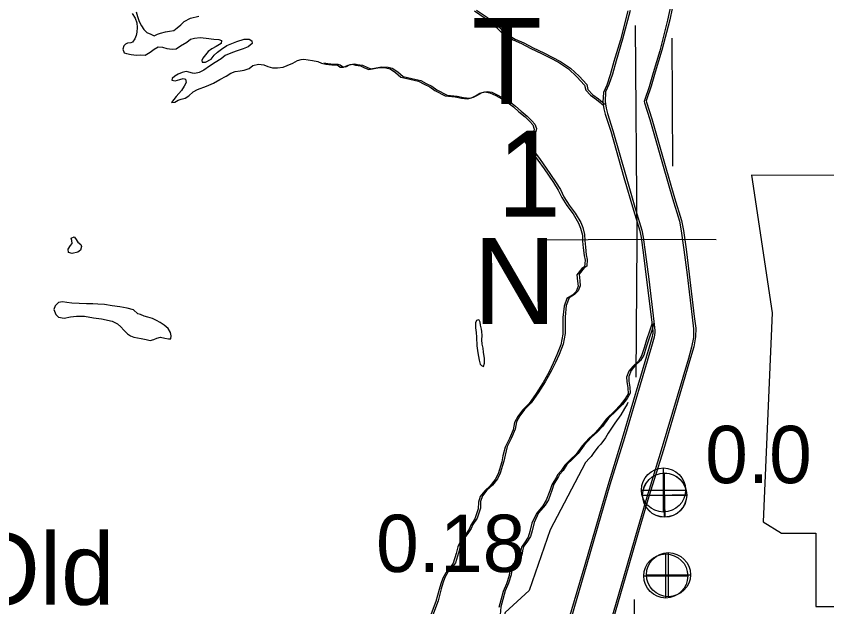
# Model space of a CAD drawing. Extents: x 1127717 to 1741049, y 2026793 to 2244711.
# Drawn here: x 1243987 to 1246972, y 2125542 to 2127719 of the extents above; entities that cross this region are included whole.
import ezdxf

# ---------------------------------------------------------------- set-up
doc = ezdxf.new("R2010")
doc.units = 0
for name, color, linetype in [('10', 7, 'Continuous'), ('2', 7, 'Continuous'), ('21', 7, 'Continuous'), ('25', 7, 'Continuous'), ('26', 7, 'Continuous'), ('30', 7, 'Continuous'), ('5', 7, 'Continuous'), ('58', 7, 'Continuous'), ('9', 7, 'Continuous')]:
    doc.layers.add(name, color=color, linetype=linetype)

msp = doc.modelspace()

# ---------------------------------------------------------------- linework, layer by layer
at = {"layer": '10'}
for points in [[(1246412.5, 2127829.6), (1246385.7, 2127703.7), (1246356.7, 2127591.2), (1246332.3, 2127510.3), (1246317.9, 2127458.3), (1246300.7, 2127408.5), (1246299, 2127404.7), (1246300.3, 2127399.3), (1246320.2, 2127338.8), (1246369, 2127166.2), (1246403.7, 2127047.3), (1246429, 2126963.9), (1246436, 2126927.3), (1246445.7, 2126858.2), (1246457.4, 2126765.6), (1246475.9, 2126610.1), (1246481.7, 2126566.4), (1246481, 2126535.3), (1246474, 2126498.6), (1246462.1, 2126457.2), (1246362.3, 2126119.1), (1246308.9, 2125945.9), (1246276, 2125832.9), (1246224.7, 2125655.6), (1246156.5, 2125423.3)], [(1246420.3, 2127831.9), (1246393.6, 2127706), (1246364.5, 2127593.5), (1246340.2, 2127512.6), (1246325.7, 2127460.6), (1246308.6, 2127410.8), (1246306.8, 2127407), (1246308.2, 2127401.6), (1246328.1, 2127341.1), (1246376.8, 2127168.5), (1246411.5, 2127049.6), (1246436.8, 2126966.2), (1246443.8, 2126929.6), (1246453.5, 2126860.5), (1246465.3, 2126767.9), (1246483.7, 2126612.4), (1246489.5, 2126568.7), (1246488.8, 2126537.6), (1246481.8, 2126500.9), (1246469.9, 2126459.5), (1246370.1, 2126121.4), (1246316.8, 2125948.2), (1246283.8, 2125835.2), (1246232.5, 2125657.9), (1246164.4, 2125425.6)], [(1246239.7, 2127738.1), (1246212.2, 2127631.6), (1246188.2, 2127551.9), (1246174.6, 2127502.9), (1246161.4, 2127464.7), (1246149.2, 2127438.3), (1246147.8, 2127402.2), (1246151.1, 2127377.6), (1246156.2, 2127357.5), (1246176.7, 2127295), (1246224.8, 2127124.9), (1246259.9, 2127004.5), (1246283.1, 2126928), (1246287.9, 2126902.8), (1246297, 2126838.3), (1246308.6, 2126747.3), (1246327.1, 2126591.4), (1246331.5, 2126558.2), (1246331.3, 2126551.3), (1246327.9, 2126533.5), (1246318, 2126499.2), (1246218.7, 2126162.4), (1246165.3, 2125989), (1246131.9, 2125874.8), (1246080.6, 2125697.5), (1246012.5, 2125465.1)], [(1246247.5, 2127740.4), (1246220, 2127633.9), (1246196.1, 2127554.2), (1246182.5, 2127505.2), (1246169.2, 2127467), (1246157, 2127440.6), (1246155.6, 2127404.5), (1246159, 2127379.9), (1246164, 2127359.8), (1246184.6, 2127297.3), (1246232.6, 2127127.2), (1246267.7, 2127006.8), (1246291, 2126930.3), (1246295.8, 2126905.1), (1246304.9, 2126840.6), (1246316.4, 2126749.6), (1246334.9, 2126593.7), (1246339.3, 2126560.5), (1246339.2, 2126553.5), (1246335.8, 2126535.8), (1246325.9, 2126501.5), (1246226.5, 2126164.7), (1246173.1, 2125991.3), (1246139.8, 2125877), (1246088.5, 2125699.8), (1246020.3, 2125467.4)]]:
    msp.add_lwpolyline(points, dxfattribs=at)
at = {"layer": '2'}
msp.add_line((1246405.6, 2127166.5), (1246402.2, 2127638.5), dxfattribs=at)
msp.add_lwpolyline([(1246239.7, 2126294.9), (1246236.2, 2126289.7), (1246227.1, 2126273.5), (1246213.6, 2126250.2), (1246191.9, 2126219.3), (1246167.2, 2126182.2), (1246157.1, 2126165.5), (1246139.9, 2126142), (1246130, 2126132.4), (1246114.2, 2126110.4), (1246104.5, 2126096.5), (1246098.1, 2126089.5), (1246083.2, 2126074.6), (1245952.7, 2125825.4), (1245876.4, 2125602.7), (1245787.4, 2125521.7), (1245741.7, 2125346.1), (1245716.8, 2125181.3), (1245740, 2125086.5), (1245765.3, 2125049), (1245723.4, 2124908.3), (1245719.7, 2124780.5), (1245668.2, 2124498.3), (1245667.1, 2124343.4)], dxfattribs=at)
at = {"layer": '21'}
msp.add_lwpolyline([(1246695.1, 2127133.1), (1246771.2, 2126625.6), (1246737.4, 2125855.8), (1246805, 2125813.5), (1246931.9, 2125813.5), (1246931.9, 2125542.8), (1247997.7, 2125542.8), (1248048.5, 2125652.8), (1248031.6, 2125830.4), (1248057, 2126033.4), (1248150, 2126194.1), (1248209.2, 2126312.6), (1248293.8, 2126439.5), (1248344.6, 2126574.8), (1248386.9, 2126684.8), (1248463, 2126777.8), (1248479.9, 2126837), (1248446.1, 2126879.3), (1248183.8, 2126879.3), (1248243, 2126997.7), (1248251.5, 2127073.9), (1248216.4, 2127132.3)], close=True, dxfattribs=at)
at = {"layer": '25'}
for p, q in [((1246376.8, 2125872.7), (1246373, 2126035.5)), ((1246293.5, 2125952.2), (1246456.3, 2125956))]:
    msp.add_line(p, q, dxfattribs=at)
msp.add_circle((1246374.9, 2125954.1), 81.4, dxfattribs=at)
at = {"layer": '26'}
for p, q in [((1246370.8, 2125891.4), (1246370.8, 2126053.9)), ((1246374.9, 2125872.8), (1246374.9, 2126035.3)), ((1246289.5, 2125972.7), (1246452, 2125972.7)), ((1246293.7, 2125954.1), (1246456.2, 2125954.1)), ((1246378.8, 2125574.6), (1246378.8, 2125737.1)), ((1246388.7, 2125579.5), (1246388.7, 2125742)), ((1246297.6, 2125655.9), (1246460.1, 2125655.9)), ((1246307.4, 2125660.7), (1246469.9, 2125660.7))]:
    msp.add_line(p, q, dxfattribs=at)
for centre in [(1246370.8, 2125972.7), (1246374.9, 2125954.1), (1246378.8, 2125655.9), (1246388.7, 2125660.7)]:
    msp.add_circle(centre, 81.2, dxfattribs=at)
at = {"layer": '5'}
for points in [[(1246266.1, 2127684.8), (1246272.9, 2126893.9), (1246269, 2126389)], [(1245915.1, 2126894.5), (1246271.8, 2126896.9), (1246564.4, 2126896.1)], [(1246262.8, 2125569.3), (1246262.7, 2125554), (1246267.9, 2124748.2)]]:
    msp.add_lwpolyline(points, dxfattribs=at)
at = {"layer": '9'}
for points in [[(1244414.1, 2127729.4), (1244424.6, 2127712.2), (1244430.6, 2127694.3), (1244432, 2127677.8), (1244431.1, 2127659.8), (1244427.9, 2127647.2), (1244423.8, 2127635.5), (1244415.1, 2127623.8), (1244408.2, 2127620.6), (1244396.8, 2127619.2), (1244389.4, 2127615.5), (1244383.1, 2127609.3), (1244379.9, 2127597.7), (1244383.8, 2127584.3), (1244392.9, 2127581.6), (1244410.5, 2127577.6), (1244429.5, 2127575.1), (1244443.5, 2127576.5), (1244461.5, 2127575), (1244479.6, 2127586.1), (1244495.3, 2127597.6), (1244510, 2127605.5), (1244526, 2127605), (1244541.6, 2127599.4), (1244561.2, 2127597), (1244576.1, 2127598.4), (1244592.2, 2127609.9), (1244614.8, 2127623.6), (1244629, 2127634), (1244643.3, 2127638.4), (1244664.7, 2127641), (1244686.8, 2127638.2), (1244714.8, 2127634), (1244733.4, 2127632.5), (1244742.9, 2127628.8), (1244741.7, 2127618.7), (1244723.6, 2127607.2), (1244707.4, 2127599.2), (1244694.2, 2127589.3), (1244684.1, 2127576), (1244674.4, 2127564.7), (1244670.7, 2127555.6), (1244671.8, 2127550.1), (1244684.3, 2127549.5), (1244705, 2127561.1), (1244716, 2127575.9), (1244728.2, 2127586.3), (1244742.3, 2127597.7), (1244762.4, 2127610.8), (1244799.4, 2127625.4), (1244826.1, 2127634.2), (1244845.1, 2127633.7), (1244854.8, 2127628.5), (1244856.1, 2127618.5), (1244841.4, 2127606.6), (1244822.7, 2127599), (1244796.5, 2127589.8), (1244777.2, 2127582.7), (1244756.5, 2127573.6), (1244740.9, 2127562.1), (1244719.8, 2127548.5), (1244698.2, 2127534.8), (1244678.2, 2127519.7), (1244660, 2127511.2), (1244644.6, 2127507.7), (1244636.1, 2127509.5), (1244622.5, 2127513.1), (1244612, 2127514.8), (1244597.6, 2127511.9), (1244583.3, 2127505.5), (1244570.5, 2127497.6), (1244560.8, 2127489.3), (1244560, 2127482.7), (1244571.5, 2127480.1), (1244589.8, 2127486.1), (1244601.2, 2127489.5), (1244610.3, 2127487.2), (1244612.6, 2127474.3), (1244605, 2127461.5), (1244595.5, 2127445.7), (1244585.8, 2127434.4), (1244576.2, 2127422.6), (1244558.8, 2127401.1), (1244571.3, 2127402.4), (1244582.6, 2127409.8), (1244593.9, 2127413.1), (1244608.8, 2127417.1), (1244623, 2127425), (1244638.6, 2127440), (1244653.8, 2127448.9), (1244687.4, 2127460.9), (1244713, 2127472.2), (1244737.1, 2127485.9), (1244760.2, 2127497.6), (1244776.9, 2127509.1), (1244792.7, 2127514.5), (1244811.6, 2127517.6), (1244826.5, 2127520), (1244844.2, 2127526.6)], [(1244428.4, 2127735.3), (1244433.9, 2127717.5), (1244439.4, 2127699.6), (1244447.9, 2127682.8), (1244456.7, 2127670), (1244467.5, 2127658.8), (1244482.2, 2127652.3), (1244495.3, 2127647.1), (1244507.6, 2127653), (1244518, 2127656.8), (1244536.8, 2127661.4), (1244550.7, 2127663.8), (1244566.6, 2127666.2), (1244579.8, 2127676.1), (1244593, 2127687.5), (1244605.6, 2127698.9), (1244628.7, 2127711.1), (1244659.5, 2127719.5)], [(1245674.2, 2127738.9), (1245714.4, 2127711.6), (1245754.8, 2127678.2), (1245777.5, 2127655.3), (1245816.6, 2127631.4), (1245847.9, 2127618.8), (1245882.4, 2127599.8), (1245921.9, 2127581.4), (1245953.3, 2127565.8)], [(1245682.1, 2127741.2), (1245722.3, 2127713.8), (1245762.7, 2127680.5), (1245785.3, 2127657.6), (1245824.4, 2127633.7), (1245855.8, 2127621.1), (1245890.3, 2127602), (1245929.7, 2127583.7), (1245961.1, 2127568)], [(1244844.2, 2127526.6), (1244858.4, 2127537.5), (1244878.7, 2127542.1), (1244898.8, 2127540.2), (1244912.9, 2127533.1), (1244931, 2127528.6), (1244949.5, 2127529.1), (1244969.4, 2127531.2), (1244985.2, 2127536.7), (1245005.9, 2127545.8), (1245022.1, 2127555.3), (1245036.5, 2127559.7), (1245046.4, 2127560.5), (1245078.5, 2127555.9), (1245097.6, 2127551.4), (1245111.3, 2127545.3), (1245126.8, 2127541.8), (1245149.3, 2127539.9), (1245163.8, 2127539.3), (1245171.9, 2127537.1), (1245180, 2127531.3), (1245192.5, 2127530.7), (1245209.3, 2127538.7), (1245225.7, 2127541.6), (1245235.7, 2127538.4), (1245254.3, 2127536), (1245270, 2127528.9), (1245285.1, 2127522.8), (1245304.5, 2127526.4), (1245324.8, 2127530), (1245348.4, 2127528.2), (1245363.9, 2127524.6), (1245383.8, 2127511.2), (1245403.8, 2127494.2), (1245436.4, 2127486.7), (1245468.6, 2127479.1), (1245488.9, 2127468.1), (1245510.1, 2127458.2), (1245528, 2127445.2), (1245566, 2127425.3), (1245603, 2127421.4), (1245626.6, 2127417.1), (1245648.2, 2127414.2), (1245663.5, 2127418.1), (1245678.3, 2127425.1), (1245694.5, 2127435.5), (1245712.8, 2127439.6), (1245730.4, 2127436.1), (1245753.1, 2127426.2), (1245775, 2127413.8), (1245798.8, 2127399.5), (1245817.7, 2127385), (1245838.2, 2127366.1), (1245861.2, 2127347.7), (1245878.2, 2127330.7), (1245889, 2127318.5), (1245894.5, 2127303.1), (1245892.3, 2127292.1), (1245888.6, 2127283.4), (1245874.8, 2127274), (1245860.1, 2127267.1), (1245861, 2127254.1), (1245887.5, 2127216.8), (1245908.3, 2127188.4), (1245931.2, 2127156), (1245965.1, 2127105.9), (1245982.9, 2127077.8), (1245995.6, 2127050.7), (1246015, 2127020.7), (1246037.8, 2126990.3), (1246057.7, 2126956.3), (1246065.3, 2126938), (1246072, 2126912.2), (1246072.6, 2126890.2), (1246075.3, 2126865.7), (1246078.2, 2126836.7), (1246081.7, 2126819.8), (1246079.9, 2126795.2), (1246070.1, 2126789.4)], [(1245953.3, 2127565.8), (1245983.7, 2127549.6), (1246020.3, 2127525.1), (1246051.6, 2127496), (1246080, 2127464.3), (1246084.5, 2127445.9), (1246102, 2127427.3), (1246123.4, 2127412.4), (1246137.8, 2127400.3), (1246147.1, 2127391.3)], [(1245961.1, 2127568), (1245991.5, 2127551.9), (1246028.2, 2127527.4), (1246059.5, 2127498.3), (1246087.9, 2127466.6), (1246092.4, 2127448.2), (1246109.9, 2127429.6), (1246131.3, 2127414.7), (1246145.6, 2127402.6), (1246157.8, 2127390.8)], [(1245120, 2127547.4), (1245134.7, 2127544.1), (1245157.2, 2127542.2), (1245171.7, 2127541.6), (1245179.7, 2127539.4), (1245187.9, 2127533.6), (1245200.4, 2127532.9), (1245217.1, 2127540.9), (1245233.5, 2127543.9), (1245243.6, 2127540.7), (1245262.1, 2127538.2), (1245277.8, 2127531.2), (1245293, 2127525.1), (1245312.3, 2127528.7), (1245332.7, 2127532.3), (1245356.2, 2127530.5), (1245371.8, 2127526.9), (1245391.6, 2127513.5), (1245411.6, 2127496.5), (1245444.3, 2127488.9), (1245476.4, 2127481.4), (1245496.7, 2127470.4), (1245518, 2127460.5), (1245535.8, 2127447.5), (1245573.8, 2127427.6), (1245610.9, 2127423.7), (1245634.5, 2127419.3), (1245656, 2127416.5), (1245671.4, 2127420.4), (1245686.1, 2127427.4), (1245702.3, 2127437.8), (1245720.7, 2127441.9), (1245738.2, 2127438.4), (1245761, 2127428.5), (1245782.8, 2127416.1), (1245806.7, 2127401.8), (1245825.6, 2127387.3), (1245846.1, 2127368.4), (1245869.1, 2127350), (1245886.1, 2127333), (1245896.9, 2127320.8), (1245902.3, 2127305.4), (1245900.1, 2127294.3), (1245896.4, 2127285.7), (1245882.7, 2127276.3), (1245867.9, 2127269.4), (1245868.8, 2127256.4), (1245895.3, 2127219.1), (1245916.1, 2127190.6), (1245939, 2127158.3), (1245972.9, 2127108.2), (1245990.7, 2127080.1), (1246003.5, 2127053), (1246022.8, 2127023), (1246045.6, 2126992.6), (1246065.6, 2126958.6), (1246073.1, 2126940.3), (1246079.9, 2126914.5), (1246080.5, 2126892.4), (1246083.2, 2126868), (1246086, 2126839), (1246089.5, 2126822.1), (1246087.7, 2126797.5), (1246077.9, 2126791.7)], [(1244214.2, 2126885.8), (1244224.9, 2126877.6), (1244227.6, 2126869.6), (1244222.9, 2126857), (1244213.6, 2126849.3), (1244192.7, 2126844.3), (1244179.7, 2126848.5), (1244177.9, 2126859.9), (1244186, 2126874.2), (1244192.4, 2126880.8), (1244191.1, 2126891.8), (1244188.9, 2126901.3), (1244200.2, 2126906), (1244205.4, 2126900.1)], [(1244205.4, 2126900.1), (1244214.2, 2126885.8)], [(1246070.1, 2126789.4), (1246051.8, 2126765.9), (1246054.5, 2126741.9), (1246056.5, 2126723.4), (1246049.1, 2126704.7), (1246035, 2126691.3), (1246014.9, 2126678.1), (1246004.7, 2126650.8), (1246000.4, 2126609.1), (1246000.2, 2126583.1), (1246000.2, 2126547), (1245992.8, 2126507.7), (1245978, 2126470.3), (1245964.8, 2126440.8), (1245949.3, 2126408.3), (1245927, 2126368.6), (1245901.7, 2126328.3), (1245875.8, 2126292), (1245851, 2126267.3), (1245833.8, 2126243.7), (1245821.4, 2126221.3), (1245816.7, 2126195.1), (1245803.2, 2126162.2), (1245787.1, 2126130.2), (1245779.1, 2126098.4), (1245774.7, 2126076.7), (1245761.5, 2126032.8), (1245751.1, 2126012), (1245732.8, 2125988.4), (1245712.4, 2125969.8), (1245696, 2125948.8), (1245689.1, 2125928.5), (1245688.4, 2125903), (1245675.9, 2125867.1), (1245661.1, 2125843.6), (1245654.6, 2125828.4), (1245642.6, 2125810), (1245625.8, 2125789), (1245613.5, 2125763.6), (1245607.3, 2125738.9), (1245596.3, 2125702.5), (1245582.4, 2125682.6), (1245568.9, 2125667.1), (1245558, 2125648.3), (1245550.1, 2125626.5), (1245544.2, 2125606.3), (1245532.5, 2125561.9), (1245511.6, 2125506.2)], [(1246077.9, 2126791.7), (1246059.6, 2126768.1), (1246062.3, 2126744.2), (1246064.3, 2126725.7), (1246056.9, 2126707), (1246042.8, 2126693.5), (1246022.7, 2126680.4), (1246012.5, 2126653.1), (1246008.2, 2126611.4), (1246008, 2126585.4), (1246008, 2126549.3), (1246000.7, 2126510), (1245985.8, 2126472.5), (1245972.7, 2126443.1), (1245957.1, 2126410.6), (1245934.8, 2126370.9), (1245909.5, 2126330.6), (1245883.6, 2126294.3), (1245858.9, 2126269.5), (1245841.6, 2126246), (1245829.3, 2126223.6), (1245824.5, 2126197.4), (1245811, 2126164.5), (1245795, 2126132.5), (1245786.9, 2126100.7), (1245782.5, 2126079), (1245769.3, 2126035.1), (1245759, 2126014.2), (1245740.7, 2125990.7), (1245720.2, 2125972.1), (1245703.9, 2125951.1), (1245697, 2125930.8), (1245696.2, 2125905.3), (1245683.8, 2125869.3), (1245669, 2125845.9), (1245662.4, 2125830.7), (1245650.5, 2125812.3), (1245633.6, 2125791.3), (1245621.4, 2125765.9), (1245615.1, 2125741.2), (1245604.2, 2125704.8), (1245590.3, 2125684.8), (1245576.7, 2125669.4), (1245565.8, 2125650.6), (1245557.9, 2125628.8), (1245552, 2125608.6), (1245540.3, 2125564.2), (1245519.5, 2125508.5)], [(1244418.3, 2126636.8), (1244395.2, 2126643.3), (1244368.1, 2126648.2), (1244340.1, 2126651), (1244311.5, 2126655.8), (1244287.5, 2126657.8), (1244268.5, 2126658.8), (1244246.1, 2126658.8), (1244219.1, 2126660.1), (1244191.6, 2126661), (1244173.6, 2126663.6), (1244157.1, 2126666.7), (1244142.2, 2126663.8), (1244130, 2126652), (1244125.8, 2126638.4), (1244133.2, 2126620.1), (1244142.4, 2126610.3), (1244163.5, 2126606.3), (1244186.8, 2126610.8), (1244208.7, 2126613.3), (1244238.2, 2126613), (1244271.8, 2126607.3), (1244300.3, 2126603.5), (1244339.9, 2126594.4), (1244359.6, 2126584.9), (1244371.9, 2126573.6), (1244383.2, 2126561.4), (1244396.5, 2126548.2), (1244408.1, 2126541), (1244419.7, 2126536.2)], [(1244419.7, 2126536.2), (1244446.7, 2126531), (1244465.3, 2126527), (1244479.9, 2126523.9), (1244493.2, 2126527.8), (1244505.1, 2126532.7), (1244518.5, 2126536.1), (1244534.6, 2126532), (1244547.1, 2126529.4), (1244555.6, 2126530.1), (1244557.3, 2126540.7), (1244554.4, 2126553.6), (1244546, 2126568.4), (1244531.7, 2126580.5), (1244516.9, 2126590.1), (1244503.2, 2126597.2), (1244489, 2126604.3), (1244471.4, 2126609.3), (1244458.3, 2126613.9), (1244444.2, 2126620), (1244434.1, 2126621.7), (1244418.3, 2126636.8)], [(1245707.6, 2126427.9), (1245710.8, 2126440.5), (1245710.8, 2126457), (1245707.6, 2126480.9), (1245706.2, 2126495.4), (1245702.8, 2126510.3), (1245701.8, 2126526.8), (1245703.3, 2126541.9), (1245701.4, 2126556.9), (1245700.7, 2126564.9), (1245697.2, 2126580.3), (1245694.9, 2126590.7), (1245692.2, 2126599.2), (1245687.7, 2126600.5), (1245682.3, 2126597.4), (1245678.5, 2126589.3), (1245678.6, 2126570.2), (1245681, 2126553.8), (1245682, 2126535.8), (1245683, 2126503.8), (1245686.7, 2126477.8), (1245691.5, 2126451.4), (1245694.9, 2126436), (1245700, 2126432.1)], [(1246327.4, 2126583.9), (1246319.4, 2126557.8), (1246308.3, 2126526.4), (1246299.2, 2126496.6), (1246290, 2126467.8), (1246278.1, 2126447.9), (1246257.2, 2126428.3), (1246243.2, 2126410.8), (1246234.9, 2126388.6), (1246235.4, 2126372.1), (1246239, 2126349.6), (1246240.2, 2126327.6), (1246228.8, 2126307.3), (1246211.4, 2126285.7), (1246190.1, 2126263.1), (1246160.5, 2126235.2), (1246137.9, 2126204), (1246119, 2126183.9), (1246096.6, 2126163.7), (1246071, 2126135.9), (1246048.4, 2126105.2), (1246027.5, 2126084.6), (1246006.7, 2126063.9), (1245992.8, 2126042.5), (1245979.8, 2126028.1), (1245976.5, 2126020), (1245958.8, 2125992.4), (1245952, 2125969.2), (1245939, 2125934.8), (1245926.6, 2125914.9), (1245903, 2125886.2), (1245886.1, 2125850.6), (1245878.9, 2125820.4), (1245872.6, 2125799.1), (1245859.2, 2125778.2), (1245847.7, 2125761.9), (1245843.6, 2125746.2), (1245841.1, 2125730.1), (1245832.1, 2125714.8), (1245817.5, 2125700.9), (1245804.1, 2125680), (1245801.8, 2125657.9), (1245792.2, 2125627), (1245780, 2125599.2), (1245771, 2125566.3), (1245764.2, 2125540.1)], [(1246335.6, 2126587.4), (1246327.2, 2126560.1), (1246316.1, 2126528.7), (1246307, 2126498.9), (1246297.9, 2126470.1), (1246286, 2126450.2), (1246265.1, 2126430.6), (1246251.1, 2126413.1), (1246242.7, 2126390.9), (1246243.2, 2126374.3), (1246246.9, 2126351.9), (1246248, 2126329.9), (1246236.6, 2126309.6), (1246219.3, 2126288), (1246198, 2126265.4), (1246168.3, 2126237.5), (1246145.8, 2126206.3), (1246126.9, 2126186.2), (1246104.5, 2126166), (1246078.8, 2126138.2), (1246056.3, 2126107.5), (1246035.4, 2126086.9), (1246014.5, 2126066.2), (1246000.7, 2126044.8), (1245987.6, 2126030.4), (1245984.3, 2126022.3), (1245966.7, 2125994.7), (1245959.9, 2125971.5), (1245946.9, 2125937.1), (1245934.5, 2125917.2), (1245910.8, 2125888.5), (1245893.9, 2125852.9), (1245886.8, 2125822.7), (1245880.4, 2125801.4), (1245867, 2125780.5), (1245855.5, 2125764.2), (1245851.5, 2125748.5), (1245849, 2125732.4), (1245839.9, 2125717.1), (1245825.4, 2125703.2), (1245812, 2125682.3), (1245809.6, 2125660.2), (1245800, 2125629.3), (1245787.9, 2125601.4), (1245778.8, 2125568.6), (1245772.1, 2125542.4), (1245769.5, 2125512.8)], [(1245700, 2126432.1), (1245707.6, 2126427.9)]]:
    msp.add_lwpolyline(points, dxfattribs=at)

# ---------------------------------------------------------------- texts
at = {"layer": '25'}
msp.add_text('0.0', height=211.2, dxfattribs=at).set_placement((1246524.2, 2125998))
at = {"layer": '30'}
for s, p in [('T', (1245664.2, 2127395.5)), ('1', (1245757.9, 2126980.7)), ('N', (1245670.1, 2126584.4))]:
    msp.add_text(s, height=316.8, dxfattribs=at).set_placement(p)
at = {"layer": '58'}
msp.add_text('0.18', height=211.2, dxfattribs=at).set_placement((1245312.1, 2125670.5))
at = {"layer": '9'}
msp.add_text('Old', height=264, dxfattribs=at).set_placement((1243798.9, 2125549.6))

doc.saveas('drawing.dxf')
